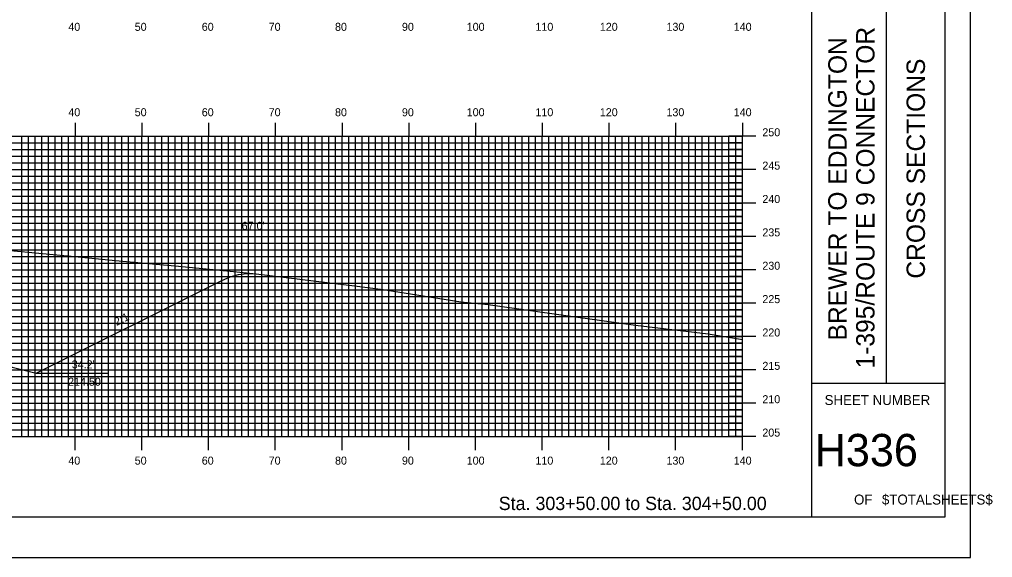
# Model space of a CAD drawing. Extents: x 1816489 to 1816833, y 442591 to 442811.
# Drawn here: x 1816686.7 to 1816832.6, y 442590.5 to 442671.2 of the extents above; entities that cross this region are included whole.
import ezdxf

# ---------------------------------------------------------------- set-up
doc = ezdxf.new("R2010")
doc.units = 0
for name, color, linetype in [('ANNOTATION', 7, 'Continuous'), ('BORDER', 7, 'Continuous'), ('D_Roadway_Centerline', 7, 'Continuous'), ('D_Roadway_SlopeLines', 7, 'Continuous'), ('D_Text_Standard', 7, 'Continuous'), ('H_V ANNOTATION', 7, 'Continuous'), ('MAJOR', 7, 'Continuous'), ('MINOR', 7, 'Continuous'), ('PDRAIN', 7, 'Continuous'), ('PLOT BOUNDARY', 7, 'Continuous'), ('S_Roadway_Centerline', 7, 'Continuous')]:
    doc.layers.add(name, color=color, linetype=linetype)

msp = doc.modelspace()

# ---------------------------------------------------------------- linework, layer by layer
at = {"layer": 'BORDER'}
for p, q in [((1816805.47, 442596.67), (1816805.47, 442806.67)), ((1816816.66, 442616.67), (1816816.66, 442686.67)), ((1816805.47, 442616.67), (1816825.47, 442616.67))]:
    msp.add_line(p, q, dxfattribs=at)
msp.add_lwpolyline([(1816505.47, 442596.67), (1816825.47, 442596.67), (1816825.47, 442806.67), (1816505.47, 442806.67)], close=True, dxfattribs=at)
at = {"layer": 'D_Roadway_Centerline'}
msp.add_lwpolyline([(1816567.65, 442643.66), (1816568.9, 442643.53), (1816570.15, 442643.26), (1816571.4, 442642.85), (1816572.65, 442642.29), (1816620.9, 442618.17), (1816624.9, 442619.17), (1816635.07, 442621.71), (1816643.07, 442622.03), (1816655.07, 442622.27), (1816667.07, 442622.03), (1816675.07, 442621.71), (1816685.25, 442619.17), (1816689.25, 442618.17), (1816717.05, 442632.07), (1816718.3, 442632.6), (1816719.55, 442632.94), (1816720.8, 442633.1), (1816722.05, 442633.06)], dxfattribs=at)
at = {"layer": 'D_Roadway_SlopeLines'}
for points in [[(1816689.25, 442618.17), (1816717.05, 442632.07), (1816718.3, 442632.6), (1816719.55, 442632.94), (1816720.8, 442633.1), (1816722.05, 442633.06)], [(1816675.07, 442621.71), (1816689.25, 442618.17)]]:
    msp.add_lwpolyline(points, dxfattribs=at)
at = {"layer": 'MAJOR'}
for p, q in [((1816695.07, 442655.67), (1816695.07, 442653.67)), ((1816705.07, 442655.67), (1816705.07, 442653.67)), ((1816715.07, 442655.67), (1816715.07, 442653.67)), ((1816725.07, 442655.67), (1816725.07, 442653.67)), ((1816735.07, 442655.67), (1816735.07, 442653.67)), ((1816745.07, 442655.67), (1816745.07, 442653.67)), ((1816755.07, 442655.67), (1816755.07, 442653.67)), ((1816765.07, 442655.67), (1816765.07, 442653.67)), ((1816775.07, 442655.67), (1816775.07, 442653.67)), ((1816785.07, 442655.67), (1816785.07, 442653.67)), ((1816795.07, 442655.67), (1816795.07, 442653.67)), ((1816515.07, 442653.67), (1816795.07, 442653.67)), ((1816515.07, 442653.67), (1816795.07, 442653.67)), ((1816695.07, 442608.67), (1816695.07, 442653.67)), ((1816705.07, 442608.67), (1816705.07, 442653.67)), ((1816715.07, 442608.67), (1816715.07, 442653.67)), ((1816725.07, 442608.67), (1816725.07, 442653.67)), ((1816735.07, 442608.67), (1816735.07, 442653.67)), ((1816745.07, 442608.67), (1816745.07, 442653.67)), ((1816755.07, 442608.67), (1816755.07, 442653.67)), ((1816765.07, 442608.67), (1816765.07, 442653.67)), ((1816775.07, 442608.67), (1816775.07, 442653.67)), ((1816785.07, 442608.67), (1816785.07, 442653.67)), ((1816797.08, 442653.67), (1816793.07, 442653.67)), ((1816795.07, 442608.67), (1816795.07, 442653.67)), ((1816795.07, 442608.67), (1816795.07, 442653.67)), ((1816515.07, 442648.67), (1816795.07, 442648.67)), ((1816797.08, 442648.67), (1816793.07, 442648.67)), ((1816515.07, 442643.67), (1816795.07, 442643.67)), ((1816797.08, 442643.67), (1816793.07, 442643.67)), ((1816515.07, 442638.67), (1816795.07, 442638.67)), ((1816797.08, 442638.67), (1816793.07, 442638.67)), ((1816515.07, 442633.67), (1816795.07, 442633.67)), ((1816797.08, 442633.67), (1816793.07, 442633.67)), ((1816515.07, 442628.67), (1816795.07, 442628.67)), ((1816797.08, 442628.67), (1816793.07, 442628.67)), ((1816515.07, 442623.67), (1816795.07, 442623.67)), ((1816797.08, 442623.67), (1816793.07, 442623.67)), ((1816515.07, 442618.67), (1816795.07, 442618.67)), ((1816797.08, 442618.67), (1816793.07, 442618.67)), ((1816515.07, 442613.67), (1816795.07, 442613.67)), ((1816797.08, 442613.67), (1816793.07, 442613.67)), ((1816515.07, 442608.67), (1816795.07, 442608.67)), ((1816515.07, 442608.67), (1816795.07, 442608.67)), ((1816695.07, 442606.66), (1816695.07, 442608.67)), ((1816705.07, 442606.66), (1816705.07, 442608.67)), ((1816715.07, 442606.66), (1816715.07, 442608.67)), ((1816725.07, 442606.66), (1816725.07, 442608.67)), ((1816735.07, 442606.66), (1816735.07, 442608.67)), ((1816745.07, 442606.66), (1816745.07, 442608.67)), ((1816755.07, 442606.66), (1816755.07, 442608.67)), ((1816765.07, 442606.66), (1816765.07, 442608.67)), ((1816775.07, 442606.66), (1816775.07, 442608.67)), ((1816785.07, 442606.66), (1816785.07, 442608.67)), ((1816797.08, 442608.67), (1816793.07, 442608.67)), ((1816795.07, 442606.66), (1816795.07, 442608.67))]:
    msp.add_line(p, q, dxfattribs=at)
at = {"layer": 'MINOR'}
for p, q in [((1816515.07, 442652.67), (1816795.07, 442652.67)), ((1816687.07, 442608.67), (1816687.07, 442653.67)), ((1816688.07, 442608.67), (1816688.07, 442653.67)), ((1816689.07, 442608.67), (1816689.07, 442653.67)), ((1816690.07, 442608.67), (1816690.07, 442653.67)), ((1816691.07, 442608.67), (1816691.07, 442653.67)), ((1816692.07, 442608.67), (1816692.07, 442653.67)), ((1816693.07, 442608.67), (1816693.07, 442653.67)), ((1816694.07, 442608.67), (1816694.07, 442653.67)), ((1816696.07, 442608.67), (1816696.07, 442653.67)), ((1816697.07, 442608.67), (1816697.07, 442653.67)), ((1816698.07, 442608.67), (1816698.07, 442653.67)), ((1816699.07, 442608.67), (1816699.07, 442653.67)), ((1816700.07, 442608.67), (1816700.07, 442653.67)), ((1816701.07, 442608.67), (1816701.07, 442653.67)), ((1816702.07, 442608.67), (1816702.07, 442653.67)), ((1816703.07, 442608.67), (1816703.07, 442653.67)), ((1816704.07, 442608.67), (1816704.07, 442653.67)), ((1816706.07, 442608.67), (1816706.07, 442653.67)), ((1816707.07, 442608.67), (1816707.07, 442653.67)), ((1816708.07, 442608.67), (1816708.07, 442653.67)), ((1816709.07, 442608.67), (1816709.07, 442653.67)), ((1816710.07, 442608.67), (1816710.07, 442653.67)), ((1816711.07, 442608.67), (1816711.07, 442653.67)), ((1816712.07, 442608.67), (1816712.07, 442653.67)), ((1816713.07, 442608.67), (1816713.07, 442653.67)), ((1816714.07, 442608.67), (1816714.07, 442653.67)), ((1816716.07, 442608.67), (1816716.07, 442653.67)), ((1816717.07, 442608.67), (1816717.07, 442653.67)), ((1816718.07, 442608.67), (1816718.07, 442653.67)), ((1816719.07, 442608.67), (1816719.07, 442653.67)), ((1816720.07, 442608.67), (1816720.07, 442653.67)), ((1816721.07, 442608.67), (1816721.07, 442653.67)), ((1816722.07, 442608.67), (1816722.07, 442653.67)), ((1816723.07, 442608.67), (1816723.07, 442653.67)), ((1816724.07, 442608.67), (1816724.07, 442653.67)), ((1816726.07, 442608.67), (1816726.07, 442653.67)), ((1816727.07, 442608.67), (1816727.07, 442653.67)), ((1816728.07, 442608.67), (1816728.07, 442653.67)), ((1816729.07, 442608.67), (1816729.07, 442653.67)), ((1816730.07, 442608.67), (1816730.07, 442653.67)), ((1816731.07, 442608.67), (1816731.07, 442653.67)), ((1816732.07, 442608.67), (1816732.07, 442653.67)), ((1816733.07, 442608.67), (1816733.07, 442653.67)), ((1816734.07, 442608.67), (1816734.07, 442653.67)), ((1816736.07, 442608.67), (1816736.07, 442653.67)), ((1816737.07, 442608.67), (1816737.07, 442653.67)), ((1816738.07, 442608.67), (1816738.07, 442653.67)), ((1816739.07, 442608.67), (1816739.07, 442653.67)), ((1816740.07, 442608.67), (1816740.07, 442653.67)), ((1816741.07, 442608.67), (1816741.07, 442653.67)), ((1816742.07, 442608.67), (1816742.07, 442653.67)), ((1816743.07, 442608.67), (1816743.07, 442653.67)), ((1816744.07, 442608.67), (1816744.07, 442653.67)), ((1816746.07, 442608.67), (1816746.07, 442653.67)), ((1816747.07, 442608.67), (1816747.07, 442653.67)), ((1816748.07, 442608.67), (1816748.07, 442653.67)), ((1816749.07, 442608.67), (1816749.07, 442653.67)), ((1816750.07, 442608.67), (1816750.07, 442653.67)), ((1816751.07, 442608.67), (1816751.07, 442653.67)), ((1816752.07, 442608.67), (1816752.07, 442653.67)), ((1816753.07, 442608.67), (1816753.07, 442653.67)), ((1816754.07, 442608.67), (1816754.07, 442653.67)), ((1816756.07, 442608.67), (1816756.07, 442653.67)), ((1816757.07, 442608.67), (1816757.07, 442653.67)), ((1816758.07, 442608.67), (1816758.07, 442653.67)), ((1816759.07, 442608.67), (1816759.07, 442653.67)), ((1816760.07, 442608.67), (1816760.07, 442653.67)), ((1816761.07, 442608.67), (1816761.07, 442653.67)), ((1816762.07, 442608.67), (1816762.07, 442653.67)), ((1816763.07, 442608.67), (1816763.07, 442653.67)), ((1816764.07, 442608.67), (1816764.07, 442653.67)), ((1816766.07, 442608.67), (1816766.07, 442653.67)), ((1816767.07, 442608.67), (1816767.07, 442653.67)), ((1816768.07, 442608.67), (1816768.07, 442653.67)), ((1816769.07, 442608.67), (1816769.07, 442653.67)), ((1816770.07, 442608.67), (1816770.07, 442653.67)), ((1816771.07, 442608.67), (1816771.07, 442653.67)), ((1816772.07, 442608.67), (1816772.07, 442653.67)), ((1816773.07, 442608.67), (1816773.07, 442653.67)), ((1816774.07, 442608.67), (1816774.07, 442653.67)), ((1816776.07, 442608.67), (1816776.07, 442653.67)), ((1816777.07, 442608.67), (1816777.07, 442653.67)), ((1816778.07, 442608.67), (1816778.07, 442653.67)), ((1816779.07, 442608.67), (1816779.07, 442653.67)), ((1816780.07, 442608.67), (1816780.07, 442653.67)), ((1816781.07, 442608.67), (1816781.07, 442653.67)), ((1816782.07, 442608.67), (1816782.07, 442653.67)), ((1816783.07, 442608.67), (1816783.07, 442653.67)), ((1816784.07, 442608.67), (1816784.07, 442653.67)), ((1816786.07, 442608.67), (1816786.07, 442653.67)), ((1816787.07, 442608.67), (1816787.07, 442653.67)), ((1816788.07, 442608.67), (1816788.07, 442653.67)), ((1816789.07, 442608.67), (1816789.07, 442653.67)), ((1816790.07, 442608.67), (1816790.07, 442653.67)), ((1816791.07, 442608.67), (1816791.07, 442653.67)), ((1816792.07, 442608.67), (1816792.07, 442653.67)), ((1816793.07, 442608.67), (1816793.07, 442653.67)), ((1816795.07, 442652.67), (1816793.07, 442652.67)), ((1816794.07, 442608.67), (1816794.07, 442653.67)), ((1816515.07, 442651.67), (1816795.07, 442651.67)), ((1816795.07, 442651.67), (1816793.07, 442651.67)), ((1816515.07, 442650.67), (1816795.07, 442650.67)), ((1816515.07, 442649.67), (1816795.07, 442649.67)), ((1816795.07, 442650.67), (1816793.07, 442650.67)), ((1816795.07, 442649.67), (1816793.07, 442649.67)), ((1816515.07, 442647.67), (1816795.07, 442647.67)), ((1816795.07, 442647.67), (1816793.07, 442647.67)), ((1816515.07, 442646.67), (1816795.07, 442646.67)), ((1816515.07, 442645.67), (1816795.07, 442645.67)), ((1816795.07, 442646.67), (1816793.07, 442646.67)), ((1816795.07, 442645.67), (1816793.07, 442645.67)), ((1816515.07, 442644.67), (1816795.07, 442644.67)), ((1816795.07, 442644.67), (1816793.07, 442644.67)), ((1816515.07, 442642.67), (1816795.07, 442642.67)), ((1816795.07, 442642.67), (1816793.07, 442642.67)), ((1816515.07, 442641.67), (1816795.07, 442641.67)), ((1816795.07, 442641.67), (1816793.07, 442641.67)), ((1816515.07, 442640.67), (1816795.07, 442640.67)), ((1816515.07, 442639.67), (1816795.07, 442639.67)), ((1816795.07, 442640.67), (1816793.07, 442640.67)), ((1816795.07, 442639.67), (1816793.07, 442639.67)), ((1816515.07, 442637.67), (1816795.07, 442637.67)), ((1816515.07, 442636.67), (1816795.07, 442636.67)), ((1816795.07, 442637.67), (1816793.07, 442637.67)), ((1816795.07, 442636.67), (1816793.07, 442636.67)), ((1816515.07, 442635.67), (1816795.07, 442635.67)), ((1816795.07, 442635.67), (1816793.07, 442635.67)), ((1816515.07, 442634.67), (1816795.07, 442634.67)), ((1816795.07, 442634.67), (1816793.07, 442634.67)), ((1816515.07, 442632.67), (1816795.07, 442632.67)), ((1816795.07, 442632.67), (1816793.07, 442632.67)), ((1816515.07, 442631.67), (1816795.07, 442631.67)), ((1816515.07, 442630.67), (1816795.07, 442630.67)), ((1816795.07, 442631.67), (1816793.07, 442631.67)), ((1816795.07, 442630.67), (1816793.07, 442630.67)), ((1816515.07, 442629.67), (1816795.07, 442629.67)), ((1816795.07, 442629.67), (1816793.07, 442629.67)), ((1816515.07, 442627.67), (1816795.07, 442627.67)), ((1816515.07, 442626.67), (1816795.07, 442626.67)), ((1816795.07, 442627.67), (1816793.07, 442627.67)), ((1816795.07, 442626.67), (1816793.07, 442626.67)), ((1816515.07, 442625.67), (1816795.07, 442625.67)), ((1816795.07, 442625.67), (1816793.07, 442625.67)), ((1816515.07, 442624.67), (1816795.07, 442624.67)), ((1816795.07, 442624.67), (1816793.07, 442624.67)), ((1816515.07, 442622.67), (1816795.07, 442622.67)), ((1816795.07, 442622.67), (1816793.07, 442622.67)), ((1816515.07, 442621.67), (1816795.07, 442621.67)), ((1816515.07, 442620.67), (1816795.07, 442620.67)), ((1816795.07, 442621.67), (1816793.07, 442621.67)), ((1816795.07, 442620.67), (1816793.07, 442620.67)), ((1816515.07, 442619.67), (1816795.07, 442619.67)), ((1816795.07, 442619.67), (1816793.07, 442619.67)), ((1816515.07, 442617.67), (1816795.07, 442617.67)), ((1816795.07, 442617.67), (1816793.07, 442617.67)), ((1816515.07, 442616.67), (1816795.07, 442616.67)), ((1816795.07, 442616.67), (1816793.07, 442616.67)), ((1816515.07, 442615.67), (1816795.07, 442615.67)), ((1816515.07, 442614.67), (1816795.07, 442614.67)), ((1816795.07, 442615.67), (1816793.07, 442615.67)), ((1816795.07, 442614.67), (1816793.07, 442614.67)), ((1816515.07, 442612.67), (1816795.07, 442612.67)), ((1816795.07, 442612.67), (1816793.07, 442612.67)), ((1816515.07, 442611.67), (1816795.07, 442611.67)), ((1816515.07, 442610.67), (1816795.07, 442610.67)), ((1816795.07, 442611.67), (1816793.07, 442611.67)), ((1816795.07, 442610.67), (1816793.07, 442610.67)), ((1816515.07, 442609.67), (1816795.07, 442609.67)), ((1816795.07, 442609.67), (1816793.07, 442609.67))]:
    msp.add_line(p, q, dxfattribs=at)
at = {"layer": 'PDRAIN'}
msp.add_line((1816689.25, 442618.17), (1816700.02, 442618.17), dxfattribs=at)
at = {"layer": 'PLOT BOUNDARY'}
msp.add_lwpolyline([(1816489.29, 442590.55), (1816829.29, 442590.55), (1816829.29, 442810.55), (1816489.29, 442810.55)], close=True, dxfattribs=at)
at = {"layer": 'S_Roadway_Centerline'}
msp.add_lwpolyline([(1816684.83, 442636.6), (1816695.53, 442635.59), (1816701.14, 442635.08), (1816711.13, 442634.15), (1816718.3, 442633.45), (1816722.22, 442633.04), (1816735.71, 442631.39), (1816736.93, 442631.24), (1816741.24, 442630.73), (1816752.9, 442628.88), (1816756.99, 442628.45), (1816768.63, 442626.79), (1816779.04, 442625.38), (1816789.94, 442624.06), (1816795.07, 442623.22)], dxfattribs=at)

# ---------------------------------------------------------------- texts
at = {"layer": 'ANNOTATION'}
msp.add_text('2:1', height=1.2, rotation=26.5651, dxfattribs=at).set_placement((1816701.29, 442625.23))
for s, p in [("34.2'", (1816694.56, 442618.89)), ('214.50', (1816694.01, 442616.29))]:
    msp.add_text(s, height=1.2, dxfattribs=at).set_placement(p)
at = {"layer": 'BORDER'}
for s, p in [('1-395/ROUTE 9 CONNECTOR', (1816814.88, 442618.87)), ('BREWER TO EDDINGTON', (1816810.7, 442623.07)), ('CROSS SECTIONS', (1816822.44, 442632.34))]:
    msp.add_text(s, height=2.7557, rotation=90, dxfattribs=at).set_placement(p)
for s, height, p in [('SHEET NUMBER', 1.4905, (1816807.4, 442613.4)), ('H336', 4.839, (1816805.91, 442604.23)), ('$TOTALSHEETS$', 1.4905, (1816815.99, 442598.49)), ('OF', 1.491, (1816811.81, 442598.49))]:
    msp.add_text(s, height=height, dxfattribs=at).set_placement(p)
at = {"layer": 'D_Text_Standard'}
msp.add_text("67.0'", height=1.2, dxfattribs=at).set_placement((1816720.03, 442639.65))
at = {"layer": 'H_V ANNOTATION'}
for s, height, p in [('40', 1.2, (1816694.05, 442669.47)), ('50', 1.2, (1816704, 442669.47)), ('60', 1.2, (1816714.05, 442669.47)), ('70', 1.2, (1816724.08, 442669.47)), ('80', 1.2, (1816734.02, 442669.47)), ('90', 1.2, (1816744.05, 442669.47)), ('100', 1.2, (1816753.76, 442669.47)), ('110', 1.2, (1816764.06, 442669.47)), ('120', 1.2, (1816773.71, 442669.47)), ('130', 1.2, (1816783.7, 442669.47)), ('140', 1.2, (1816793.78, 442669.47)), ('40', 1.2, (1816694.05, 442656.67)), ('50', 1.2, (1816704, 442656.67)), ('60', 1.2, (1816714.05, 442656.67)), ('70', 1.2, (1816724.08, 442656.67)), ('80', 1.2, (1816734.02, 442656.67)), ('90', 1.2, (1816744.05, 442656.67)), ('100', 1.2, (1816753.76, 442656.67)), ('110', 1.2, (1816764.06, 442656.67)), ('120', 1.2, (1816773.71, 442656.67)), ('130', 1.2, (1816783.7, 442656.67)), ('140', 1.2, (1816793.78, 442656.67)), ('250', 1.2, (1816798.07, 442653.67)), ('245', 1.2, (1816798.07, 442648.67)), ('240', 1.2, (1816798.07, 442643.67)), ('235', 1.2, (1816798.07, 442638.67)), ('230', 1.2, (1816798.07, 442633.67)), ('225', 1.2, (1816798.07, 442628.67)), ('220', 1.2, (1816798.07, 442623.67)), ('215', 1.2, (1816798.07, 442618.67)), ('210', 1.2, (1816798.07, 442613.67)), ('205', 1.2, (1816798.07, 442608.67)), ('40', 1.2, (1816694.05, 442604.47)), ('50', 1.2, (1816704, 442604.47)), ('60', 1.2, (1816714.05, 442604.47)), ('70', 1.2, (1816724.08, 442604.47)), ('80', 1.2, (1816734.02, 442604.47)), ('90', 1.2, (1816744.05, 442604.47)), ('100', 1.2, (1816753.76, 442604.47)), ('110', 1.2, (1816764.06, 442604.47)), ('120', 1.2, (1816773.71, 442604.47)), ('130', 1.2, (1816783.7, 442604.47)), ('140', 1.2, (1816793.78, 442604.47)), ('Sta. 303+50.00 to Sta. 304+50.00', 2.0004, (1816758.56, 442597.66))]:
    msp.add_text(s, height=height, dxfattribs=at).set_placement(p)

doc.saveas('drawing.dxf')
